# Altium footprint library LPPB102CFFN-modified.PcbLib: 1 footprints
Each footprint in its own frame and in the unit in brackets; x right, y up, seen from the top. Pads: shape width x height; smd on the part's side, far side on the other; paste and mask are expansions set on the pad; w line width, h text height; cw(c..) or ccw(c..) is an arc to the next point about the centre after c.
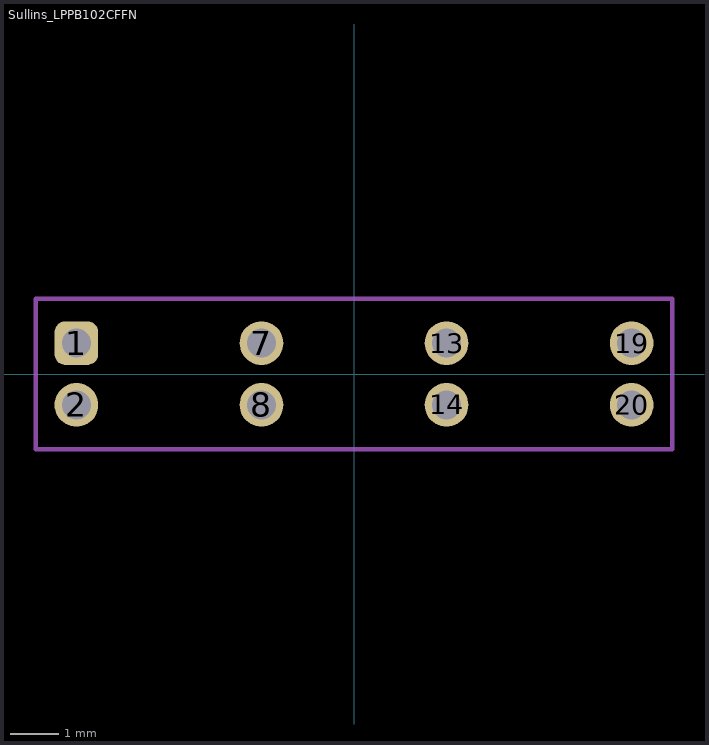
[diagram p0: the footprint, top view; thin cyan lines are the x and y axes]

## Sullins_LPPB102CFFN [mm] "Receptacle, 1.27 mm, TH"
height 4.7
pads (8):
  rrect50% 0.9x0.9 hole 0.6: 1(-5.715,0.635)
  round 0.9 hole 0.6 mask+0.102: 2(-5.715,-0.635) 8(-1.905,-0.635) 14(1.905,-0.635) 20(5.715,-0.635)
  round 0.9 hole 0.6: 7(-1.905,0.635) 13(1.905,0.635) 19(5.715,0.635)
M5 Assembly Top:
  lines w0.1: -6.55,-1.55 6.55,-1.55 6.55,1.55 -6.55,1.55 -6.55,-1.55
  text ".Designator" at -1.7,-0.4 h1.02
3D body "_ _ _B102CFFN-RC.STEP": height 4.5, standoff -3, extent -6.555,-1.565 6.545,1.535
